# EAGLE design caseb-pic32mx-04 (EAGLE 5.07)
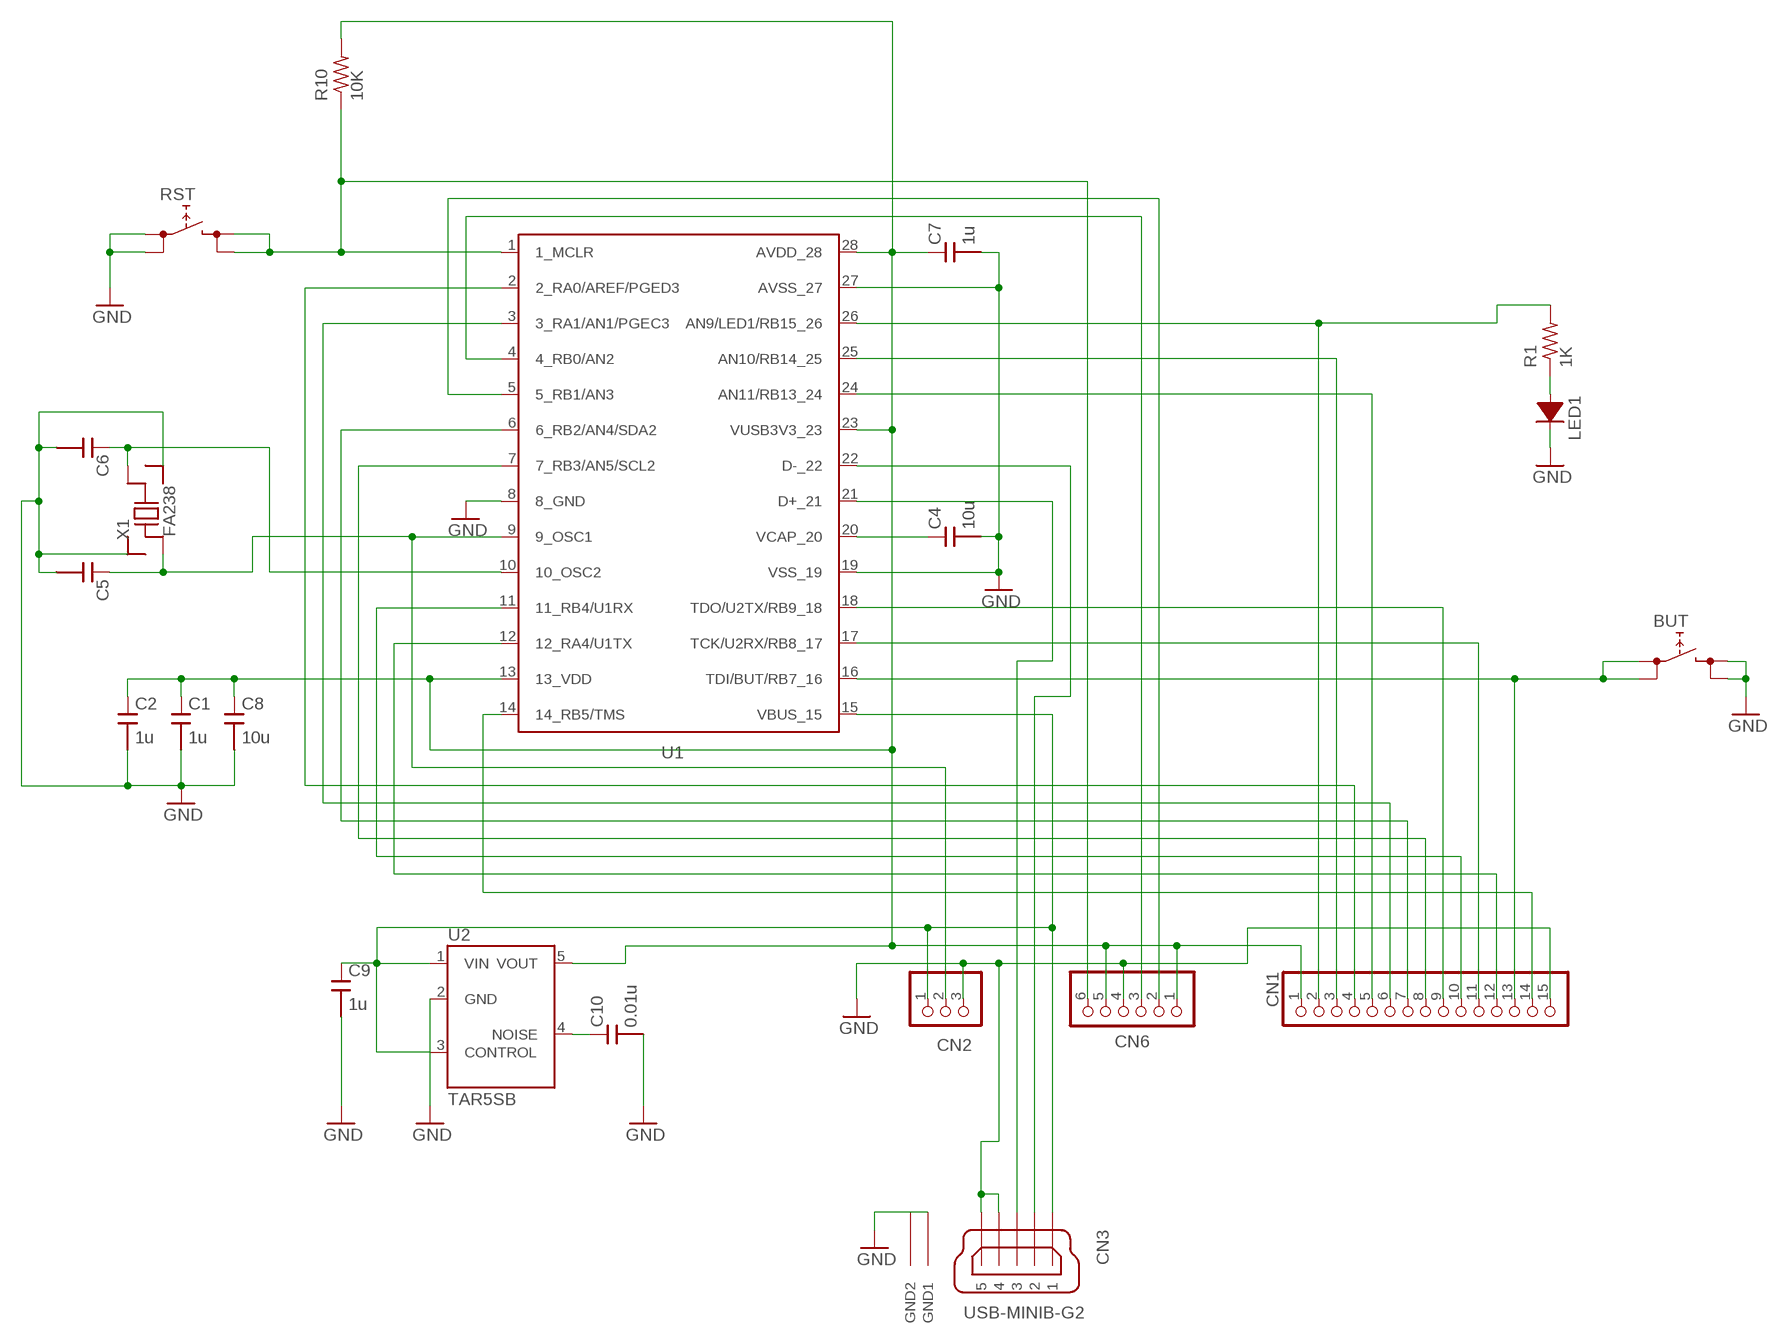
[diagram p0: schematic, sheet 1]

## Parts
BUT  TACTSWTACTSW/SMD  [TACTSW/SMD]
C1  1u  C/SMDC2012  [C2012]
C2  1u  C/SMDC2012  [C2012]
C4  10u  C/SMDC2012  [C2012]
C5  C/SMDC2012  [C2012]
C6  C/SMDC2012  [C2012]
C7  1u  C/SMDC2012  [C2012]
C8  10u  C/SMDC2012  [C2012]
C9  1u  C/SMDC2012  [C2012]
C10  0.01u  C/SMDC2012  [C2012]
CN1  PINHDR15  [PINHDRX15]
CN2  PINHDR3  [PINHDR1X3]
CN3  USB-MINIB-G2  [USB-MINIBV]
CN6  PINHDR6  [PINHDR1X6]
LED1  D/SMDRB161M  [SOD123]
R1  1K  R/SMDR2012R  [R2012R]
R10  10K  R/SMDR2012R  [R2012R]
RST  TACTSWTACTSW/SMD  [TACTSW/SMD]
U1  PIC32MX-DIP  [DIP28]
U2  TAR5SB  [SOT235]
X1  FA238  [FA238]

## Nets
GND [power]: BUT.3 BUT.4 C1.2 C2.2 C4.2 C5.2 C6.2 C7.2 C8.2 C9.2 CN1.15 CN2.3 CN3.4 CN3.5 CN3.M1(GND1) CN3.M2(GND2) CN6.4 LED1.2(C) RST.1 RST.2 U1.8(8_GND) U1.19(VSS_19) U1.27(AVSS_27) U2.2(GND) X1.2 X1.4
N$1: CN3.2 U1.22(D-_22)
N$2: BUT.1 BUT.2 CN1.13 U1.16(TDI/BUT/RB7_16)
N$4: CN1.12 U1.12(12_RA4/U1TX)
N$5: CN1.11 U1.17(TCK/U2RX/RB8_17)
N$6: LED1.1(A) R1.1
N$7: CN6.6 R10.1 RST.3 RST.4 U1.1(1_MCLR)
N$8: CN1.8 U1.7(7_RB3/AN5/SCL2)
N$9: CN1.7 U1.6(6_RB2/AN4/SDA2)
N$15: CN1.10 U1.11(11_RB4/U1RX)
N$17: C10.1 U2.4(NOISE)
N$18: C6.1 U1.10(10_OSC2) X1.3
N$19: CN1.2 R1.2 U1.26(AN9/LED1/RB15_26)
N$20: CN1.9 U1.18(TDO/U2TX/RB9_18)
N$21: CN6.2 U1.5(5_RB1/AN3)
N$23: CN1.6 U1.3(3_RA1/AN1/PGEC3)
N$24: CN1.5 U1.24(AN11/RB13_24)
N$25: CN1.4 U1.2(2_RA0/AREF/PGED3)
N$26: CN1.3 U1.25(AN10/RB14_25)
N$27: CN6.3 U1.4(4_RB0/AN2)
N$28: C5.1 CN2.2 U1.9(9_OSC1) X1.1
N$29: CN3.3 U1.21(D+_21)
N$30: CN1.14 U1.14(14_RB5/TMS)
N$31: C9.1 CN2.1 CN3.1 U1.15(VBUS_15) U2.1(VIN) U2.3(CONTROL)
VCAP_20: C4.1 U1.20(VCAP_20)
VOUT: C1.1 C2.1 C7.1 C8.1 CN1.1 CN6.1 CN6.5 R10.2 U1.13(13_VDD) U1.23(VUSB3V3_23) U1.28(AVDD_28) U2.5(VOUT)
Unconnected: C10.2

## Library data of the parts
BUT RST = SRT162-010:TACTSW: 4pin tactsw (1,2 - 3,4)
C1 C2 C4-C10 = SRT162-010:C/SMD
CN1 = SRT162-010:PINHDR15
CN2 = SRT162-010:PINHDR3
CN3 = SRT162-010:USB-MINIB-G2
CN6 = SRT162-010:PINHDR6
LED1 = SRT162-010:D/SMD
R1 R10 = SRT162-010:R/SMD
U1 = SRT162-010:PIC32MX-DIP
U2 = SRT162-010:TAR5SB
X1 = SRT162-010:FA238

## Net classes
0 default: width 0.203 mm
1 power: width 0.254 mm

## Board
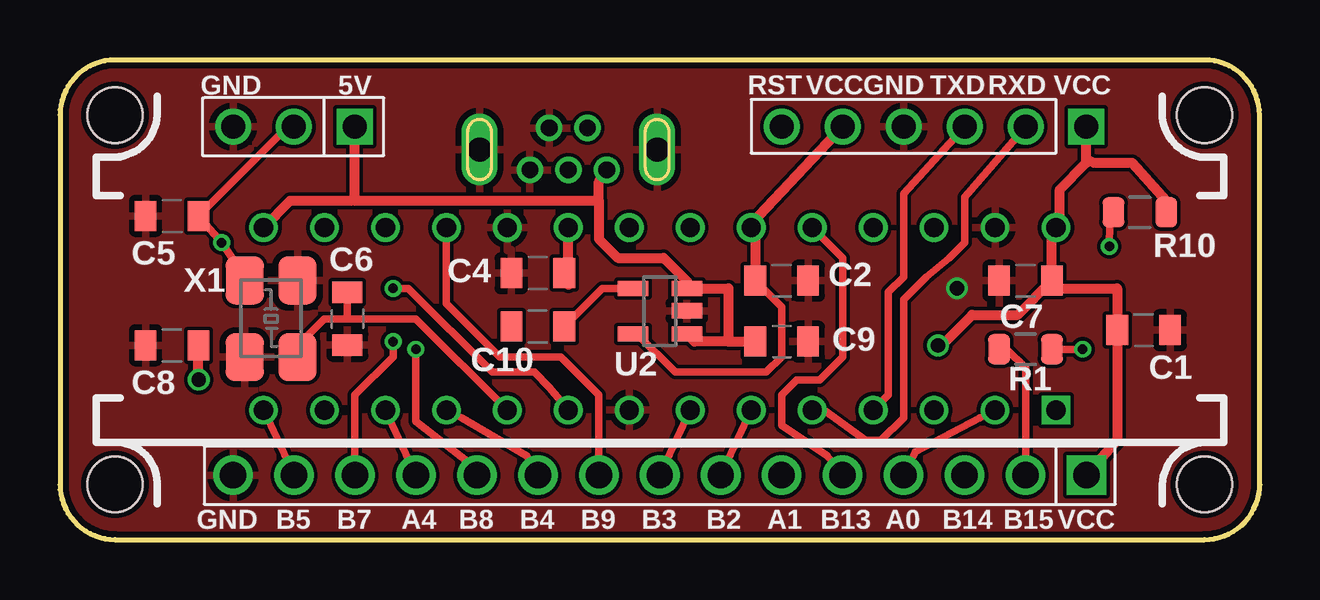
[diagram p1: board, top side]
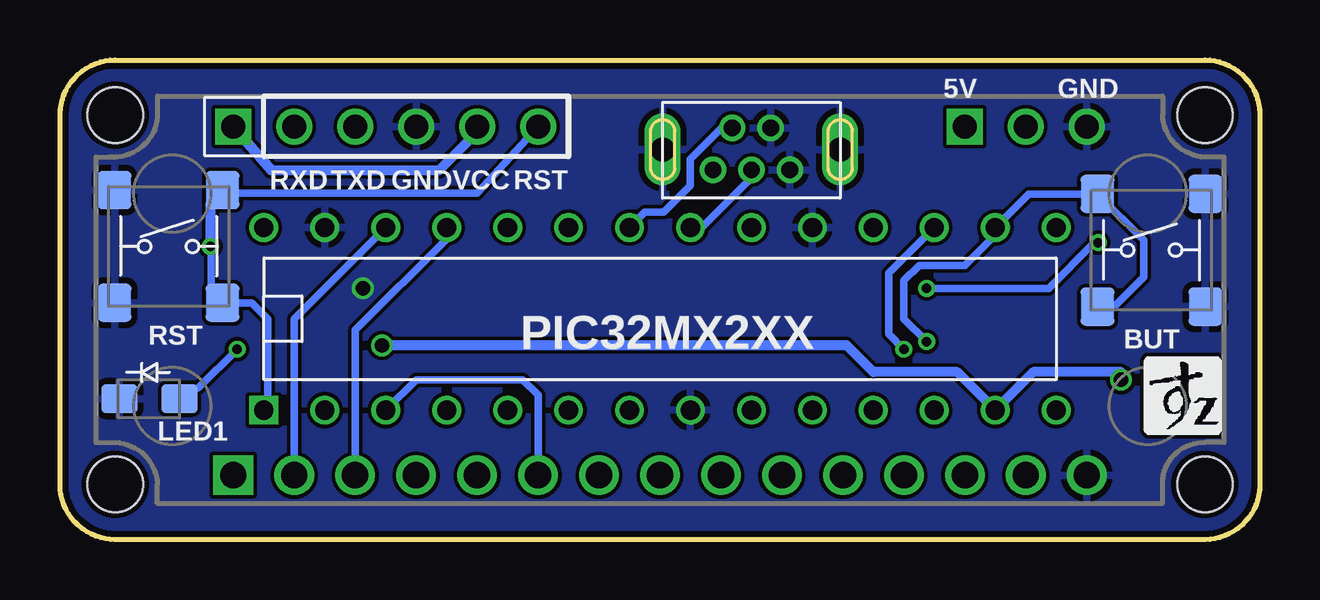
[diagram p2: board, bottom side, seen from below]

Size 49.99 x 20 mm. Coordinates in mm from the lower left corner, seen from the top.
Outline: 47.68,0 2.29,0 arc-90 0,2.3 0,17.7 arc-90 2.29,20 47.69,20 arc-90 49.98,17.7 49.98,2.3
Outline: 47.68,0 47.69,0
Outline: 47.68,0 arc90 49.99,2.3
Copper layers (1*16): Top 0.0356mm / dielectric 1.5011mm / Bottom 0.0356mm
Design rules "Fusion_v1.1 *": minimum track width 6mil, minimum drill 0.2997mm, track to track 6mil, track to pad 6mil, pad to pad 6mil, via to via 6mil, smd to smd 0mil, copper to edge 10mil, drill to drill 10mil, minimum pad ring 6mil, minimum via ring 6mil, stop-mask expansion 2mil, vias tented up to drill 100mil, thermal gap 10mil
Holes 2.3 mm at 47.69,17.7 2.29,17.7 2.29,2.3 47.69,2.3

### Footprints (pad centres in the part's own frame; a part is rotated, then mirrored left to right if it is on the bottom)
TACTSW/SMD = smd 1.4 x 1.6: 1 -2.25,2.35; 2 -2.25,-2.35; 3 2.25,2.35; 4 2.25,-2.35
C2012 = smd 0.9 x 1.25: 1 -1.1,0; 2 1.1,0
PINHDRX15 = drill 1.1 square: 1 -17.78,0 | drill 1.1 round: 2 -15.24,0; 3 -12.7,0; 4 -10.16,0; 5 -7.62,0; 6 -5.08,0; 7 -2.54,0; 8 0,0; 9 2.54,0; 10 5.08,0; 11 7.62,0; 12 10.16,0; 13 12.7,0; 14 15.24,0; 15 17.78,0
PINHDR1X3 = drill 1 square: 1 -2.54,0 | drill 1 round: 2 0,0; 3 2.54,0
USB-MINIBV = drill 0.7 pad 1.1 round: 1 -0.995,1.6; 2 0.755,0.8; 3 -0.995,0; 4 0.755,-0.8; 5 -0.995,-1.6 | drill 1 long: M1 -0.145,3.7; M2 -0.145,-3.7
PINHDR1X6 = drill 1 square: 1 -6.35,0 | drill 1 round: 2 -3.81,0; 3 -1.27,0; 4 1.27,0; 5 3.81,0; 6 6.35,0
SOD123 = smd 1.5 x 1.2: 1 -1.25,0; 2 1.25,0
R2012R = smd 0.9 x 1.25: 1 -1.1,0; 2 1.1,0
DIP28 = drill 0.8 square: 1 -16.51,-3.81 | drill 0.8 round: 2 -13.97,-3.81; 3 -11.43,-3.81; 4 -8.89,-3.81; 5 -6.35,-3.81; 6 -3.81,-3.81; 7 -1.27,-3.81; 8 1.27,-3.81; 9 3.81,-3.81; 10 6.35,-3.81; 11 8.89,-3.81; 12 11.43,-3.81; 13 13.97,-3.81; 14 16.51,-3.81; 15 16.51,3.81; 16 13.97,3.81; 17 11.43,3.81; 18 8.89,3.81; 19 6.35,3.81; 20 3.81,3.81; 21 1.27,3.81; 22 -1.27,3.81; 23 -3.81,3.81; 24 -6.35,3.81; 25 -8.89,3.81; 26 -11.43,3.81; 27 -13.97,3.81; 28 -16.51,3.81
SOT235 = smd 0.635 x 1.27: 1 -0.95,-1.125; 2 0.013,-1.135; 3 0.95,-1.125; 4 0.95,1.125; 5 -0.95,1.125
FA238 = smd 2 x 1.6: 1 -1.6,-1.1; 2 1.6,-1.1; 3 1.6,1.1; 4 -1.6,1.1

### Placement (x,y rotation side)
BUT  4.51,12.06 0 bottom
C1  45.15,8.73 0 top
C2  30.07,10.79 0 top
C4  19.91,11.11 180 top
C5  4.67,13.49 180 top
C6  11.97,9.21 270 top
C7  40.23,10.79 180 top
C8  4.67,8.1 180 top
C9  30.07,8.25 0 top
C10  19.91,8.89 180 top
CN1  24.99,2.68 180 top
CN2  9.75,17.22 180 top
CN3  21.18,16.41 90 bottom
CN6  36.42,17.22 0 bottom
LED1  46.26,5.87 180 bottom
R1  40.23,7.94 180 top
R10  44.99,13.65 0 top
RST  45.47,12.22 0 bottom
U1  24.99,9.21 0 bottom
U2  24.99,9.52 90 top
X1  8.8,9.21 270 top

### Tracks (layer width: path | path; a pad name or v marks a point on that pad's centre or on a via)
GND  (via drill 0.6)
  other vias: 37.37,10.48
  pour Bottom: -1.04,-2.7 51.34,-2.7 51.34,21.43 -1.04,21.43
  pour Top: 50.39,21.11 -0.73,21.11 -0.73,-1.11 50.39,-1.11
N$1
  Bottom 0.305: CN3.2 22.43,17.16 23.72,15.87 23.72,14.76 24.83,13.65 25.62,13.65 U1.22
N$2  (via drill 0.4)
  Top 0.305: v13.88,8.25 13.88,7.62 12.29,6.03 CN1.13
  Bottom 0.203: 10.62,12.94 10.54,13.02 10.62,13.1 10.7,13.18 U1.16 10.94,12.94
  Bottom 0.305: v13.88,8.25 14.83,9.21 14.83,10.79 14.2,11.43 12.29,11.43 11.02,12.7 U1.16 9.62,14.41 BUT.1 4.83,12.48 4.83,10.95 6.07,9.71 BUT.2 | 10.54,13.02
N$4
  Top 0.305: CN1.12 U1.12
N$5  (via drill 0.4)
  Top 0.305: CN1.11 17.38,3.02 16.89,3.33 14.83,4.92 v14.83,7.94
  Bottom 0.305: v14.83,7.94 15.46,8.57 15.46,11.11 U1.17
N$6  (via drill 0.4)
  Top 0.305: R1.1 v42.61,7.94
  Bottom 0.305: LED1.1 44.2,6.35 v42.61,7.94
N$7  (via drill 0.4)
  Top 0.305: R10.1 43.73,13.19 v43.72,12.22
  Bottom 0.203: 43.41,14.6 RST.3
  Bottom 0.305: 43.25,14.6 43.72,13.81 v43.72,12.22 43.7,12.04 43.7,9.71 RST.4 42.01,9.87 41.34,9.21 41.34,5.55 U1.1 | CN6.6 32.59,14.45 43.09,14.45 43.53,14.89 RST.3
  Bottom 0.406: 43.41,14.6 43.25,14.6 43.72,13.97 43.72,12.44
N$8
  Top 0.305: CN1.8 U1.7
N$9
  Top 0.305: CN1.7 U1.6
N$15
  Top 0.305: CN1.10 19.45,3.49 16.73,5.08 U1.11
N$17
  Top 0.305: U2.4 22.59,10.47 C10.1
N$18
  Top 0.305: U1.10 14.83,9.21 11.97,9.21 | X1.3 9.9,8.08 11.02,9.21 11.97,9.21 | 11.97,9.21 C6.1
N$19
  Top 0.305: R1.2 39.45,7.94 40.23,7.15 CN1.2
  Bottom 0.305: U1.26 40.23,9.21 CN1.2
N$20
  Top 0.305: U1.18 16.1,9.84 18.32,7.62 20.86,7.62 22.45,6.03 CN1.9
N$21
  Top 0.305: CN6.2 37.69,14.27 37.69,12.38 37.05,11.75 36.1,10.95 35.15,10 35.15,7.14 35.15,6.19 35.15,5.08 34.2,4.13 33.56,4.13 31.82,5.4 U1.5
N$23
  Bottom 0.305: U1.3 35.15,6.67 30.7,6.67 30.07,6.03 CN1.6
N$24
  Top 0.305: U1.24 32.61,11.75 32.61,7.62 31.66,6.67 30.7,6.67 30.07,6.03 30.07,4.76 31.98,3.49 CN1.5
N$25
  Top 0.305: CN1.4 35.63,3.65 38.33,5.08 U1.2
N$26
  Bottom 0.305: U1.25 34.04,12.86 33.88,12.54 37.69,8.73 CN1.3
N$27
  Top 0.305: U1.4 34.52,6.03 34.52,10.32 35.15,10.95 35.15,14.43 CN6.3
N$28  (via drill 0.4)
  Top 0.305: v13.88,10.48 14.51,10.48 18,6.98 19.75,6.98 20.39,6.35 U1.9 | v6.73,12.38 6.73,12.41 | v6.73,12.38 C5.1 9.26,16.98 CN2.2 9.75,16.84 | X1.1 7.7,10.94 v6.73,12.38
  Bottom 0.305: v6.73,12.38 6.89,12.38 8.8,10.48 v13.88,10.48
N$29
  Bottom 0.305: CN3.3 21.18,15.08 23.24,13.02 23.56,12.86 U1.21
N$30
  Top 0.305: CN1.14 U1.14
N$31
  Top 0.305: 12.13,14.13 12.29,14.29 12.29,14.13
  Top 0.406: U2.1 26.44,8.25 27.85,8.25 | 27.85,8.25 C9.1 | 27.85,8.25 27.85,10.48 U2.3 26.12,10.78 25.15,11.75 23.24,11.75 22.45,12.54 22.45,13.49 22.45,14.13 | U1.15 9.59,14.13 12.13,14.13 | 12.29,14.29 CN2.1 | 12.29,14.13 22.45,14.13 | CN3.1 22.45,14.92 22.45,14.13
VCAP_20
  Top 0.406: C4.1 21.18,10.62 U1.20
VOUT  (via drill 0.6)
  Top 0.203: U1.23 28.88,13.18
  Top 0.305: U2.5 24.03,8.57 25.62,6.98 29.44,6.98 30.07,7.62 30.07,9.69 C2.1
  Top 0.406: 42.77,15.87 42.77,15.71 41.66,14.6 41.66,12.94 U1.28 41.33,12.85 C7.1 | 42.77,15.87 CN6.1 | C1.1 43.87,9.05 | C2.1 28.97,12.87 U1.23 28.8,13.16 CN6.5 | C7.1 41.33,10.62 | v36.58,8.09 36.74,8.09 38.01,9.37 39.9,9.37 C7.1 | C1.1 44.04,8.56 | C1.1 44.05,9.21 | C1.1 44.05,10.48 41.33,10.48 C7.1 | C1.1 44.05,4.14 CN1.1 | R10.2 46.09,14.14 44.67,15.71 43.09,15.71 42.77,15.87 | v5.78,6.67 v5.77,6.68 C8.1
  Bottom 0.203: v5.78,6.67 5.78,6.82 5.78,6.98
  Bottom 0.406: v36.58,8.09 17.21,8.09 16.1,6.98 12.61,6.98 U1.13 9.43,6.98 5.78,6.98 | CN6.1 41.2,15.4 34.2,15.4 32.62,16.97
  Bottom 0.61: 32.62,16.97 CN6.5
(copper drawn outside any net)
  shapes: Bottom area x352

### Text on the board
tPlace: GND | 5V | RST | VCC | GND | TXD | RXD | VCC | GND | B5 | B7 | A4 | B8 | B4 | B9 | B3 | B2 | A1 | B13 | A0 | B14 | B15 | VCC
bPlace: GND | 5V | RST | VCC | GND | TXD | RXD | PIC32MX2XX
